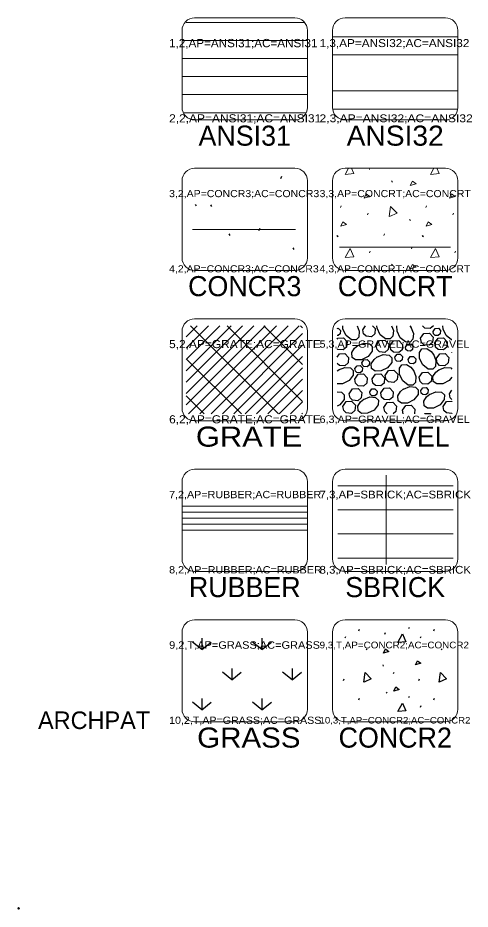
# Model space of a CAD drawing. Extents: x 95935 to 95946.4, y 95971.2 to 95974.7.
# Drawn here: x 95935.031 to 95936.835, y 95971.178 to 95974.732 of the extents above; entities that cross this region are included whole.
import ezdxf
from ezdxf.enums import TextEntityAlignment as Align

# ---------------------------------------------------------------- set-up
doc = ezdxf.new("R2010")
doc.units = 0
doc.header["$LTSCALE"] = 0.013
doc.header["$PDMODE"] = 32
doc.header["$PDSIZE"] = 0.0065
for name, color, linetype, lineweight in [('1', 7, 'Continuous', 13), ('25', 7, 'Continuous', 13), ('6', 7, 'Continuous', 13), ('63', 7, 'Continuous', 13)]:
    doc.layers.add(name, color=color, linetype=linetype, lineweight=lineweight)
doc.layers.add('20', color=7, linetype='Continuous')
doc.layers.add('8', color=7, linetype='Continuous')

msp = doc.modelspace()

# ---------------------------------------------------------------- linework, layer by layer
at = {"layer": '1'}
for p, q in [((95935.7357, 95974.7318), (95936.1357, 95974.7318)), ((95936.3357, 95974.7318), (95936.7357, 95974.7318)), ((95935.6857, 95974.3747), (95935.6857, 95974.6818)), ((95936.1857, 95974.6818), (95936.1857, 95974.3747)), ((95936.2857, 95974.3747), (95936.2857, 95974.6818)), ((95936.7857, 95974.6818), (95936.7857, 95974.3747)), ((95936.1357, 95974.3247), (95935.7357, 95974.3247)), ((95936.7357, 95974.3247), (95936.3357, 95974.3247)), ((95935.7357, 95974.1318), (95936.1357, 95974.1318)), ((95936.3357, 95974.1318), (95936.7357, 95974.1318)), ((95935.6857, 95973.7747), (95935.6857, 95974.0818)), ((95936.1857, 95974.0818), (95936.1857, 95973.7747)), ((95936.2857, 95973.7747), (95936.2857, 95974.0818)), ((95936.7857, 95974.0818), (95936.7857, 95973.7747)), ((95936.1357, 95973.7247), (95935.7357, 95973.7247)), ((95936.7357, 95973.7247), (95936.3357, 95973.7247)), ((95935.7357, 95973.5318), (95936.1357, 95973.5318)), ((95936.3357, 95973.5318), (95936.7357, 95973.5318)), ((95935.6857, 95973.1747), (95935.6857, 95973.4818)), ((95936.1857, 95973.4818), (95936.1857, 95973.1747)), ((95936.2857, 95973.1747), (95936.2857, 95973.4818)), ((95936.7857, 95973.4818), (95936.7857, 95973.1747)), ((95936.1357, 95973.1247), (95935.7357, 95973.1247)), ((95936.7357, 95973.1247), (95936.3357, 95973.1247)), ((95935.7357, 95972.9318), (95936.1357, 95972.9318)), ((95936.3357, 95972.9318), (95936.7357, 95972.9318)), ((95935.6857, 95972.5747), (95935.6857, 95972.8818)), ((95936.1857, 95972.8818), (95936.1857, 95972.5747)), ((95936.2857, 95972.5747), (95936.2857, 95972.8818)), ((95936.7857, 95972.8818), (95936.7857, 95972.5747)), ((95936.1357, 95972.5247), (95935.7357, 95972.5247)), ((95936.7357, 95972.5247), (95936.3357, 95972.5247)), ((95935.7357, 95972.3318), (95936.1357, 95972.3318)), ((95936.3357, 95972.3318), (95936.7357, 95972.3318)), ((95935.6857, 95971.9747), (95935.6857, 95972.2818)), ((95936.1857, 95972.2818), (95936.1857, 95971.9747)), ((95936.2857, 95971.9747), (95936.2857, 95972.2818)), ((95936.7857, 95972.2818), (95936.7857, 95971.9747)), ((95936.1357, 95971.9247), (95935.7357, 95971.9247)), ((95936.7357, 95971.9247), (95936.3357, 95971.9247))]:
    msp.add_line(p, q, dxfattribs=at)
for centre, start, end in [((95935.7357, 95974.6818), 90, 180), ((95936.1357, 95974.6818), 0, 90), ((95936.3357, 95974.6818), 90, 180), ((95936.7357, 95974.6818), 0, 90), ((95935.7357, 95974.3747), 180, 270), ((95936.1357, 95974.3747), 270, 0), ((95936.3357, 95974.3747), 180, 270), ((95936.7357, 95974.3747), 270, 0), ((95935.7357, 95974.0818), 90, 180), ((95936.1357, 95974.0818), 0, 90), ((95936.3357, 95974.0818), 90, 180), ((95936.7357, 95974.0818), 0, 90), ((95935.7357, 95973.7747), 180, 270), ((95936.1357, 95973.7747), 270, 0), ((95936.3357, 95973.7747), 180, 270), ((95936.7357, 95973.7747), 270, 0), ((95935.7357, 95973.4818), 90, 180), ((95936.1357, 95973.4818), 0, 90), ((95936.3357, 95973.4818), 90, 180), ((95936.7357, 95973.4818), 0, 90), ((95935.7357, 95973.1747), 180, 270), ((95936.1357, 95973.1747), 270, 0), ((95936.3357, 95973.1747), 180, 270), ((95936.7357, 95973.1747), 270, 0), ((95935.7357, 95972.8818), 90, 180), ((95936.1357, 95972.8818), 0, 90), ((95936.3357, 95972.8818), 90, 180), ((95936.7357, 95972.8818), 0, 90), ((95935.7357, 95972.5747), 180, 270), ((95936.1357, 95972.5747), 270, 0), ((95936.3357, 95972.5747), 180, 270), ((95936.7357, 95972.5747), 270, 0), ((95935.7357, 95972.2818), 90, 180), ((95936.1357, 95972.2818), 0, 90), ((95936.3357, 95972.2818), 90, 180), ((95936.7357, 95972.2818), 0, 90), ((95935.7357, 95971.9747), 180, 270), ((95936.1357, 95971.9747), 270, 0), ((95936.3357, 95971.9747), 180, 270), ((95936.7357, 95971.9747), 270, 0)]:
    msp.add_arc(centre, 0.05, start, end, dxfattribs=at)
at = {"layer": '25'}
msp.add_line((95935.7278, 95973.8875), (95936.1378, 95973.8875), dxfattribs=at)
at = {"layer": '6'}
for p, q in [((95935.7022, 95974.7136), (95936.1735, 95974.7136)), ((95935.6857, 95974.6416), (95936.1857, 95974.6416)), ((95936.2857, 95974.6561), (95936.7857, 95974.6561)), ((95935.6857, 95974.5696), (95936.1857, 95974.5696)), ((95936.2857, 95974.5841), (95936.7857, 95974.5841)), ((95935.6857, 95974.4976), (95936.1857, 95974.4976)), ((95935.6857, 95974.4256), (95936.1857, 95974.4256)), ((95936.2857, 95974.4401), (95936.7857, 95974.4401)), ((95935.6944, 95974.3536), (95936.1806, 95974.3536)), ((95936.2884, 95974.3681), (95936.7844, 95974.3681)), ((95936.3367, 95974.1077), (95936.3495, 95974.1318)), ((95936.4326, 95974.1269), (95936.4348, 95974.1318)), ((95936.677, 95974.1077), (95936.6898, 95974.1318)), ((95936.5214, 95974.0814), (95936.5243, 95974.0772)), ((95936.3175, 95973.9756), (95936.3204, 95973.982)), ((95936.6578, 95973.9756), (95936.6607, 95973.982)), ((95936.4255, 95973.9464), (95936.4284, 95973.9528)), ((95936.5944, 95973.9286), (95936.5951, 95973.9222)), ((95936.7658, 95973.9464), (95936.7687, 95973.9528)), ((95936.3026, 95973.864), (95936.3055, 95973.8598)), ((95936.3055, 95973.8624), (95936.3083, 95973.8582)), ((95936.4902, 95973.864), (95936.493, 95973.8704)), ((95936.6429, 95973.864), (95936.6458, 95973.8598)), ((95936.6458, 95973.8624), (95936.6486, 95973.8582)), ((95936.601, 95973.8114), (95936.6038, 95973.8178)), ((95936.4326, 95973.795), (95936.4355, 95973.8014)), ((95936.7729, 95973.795), (95936.7758, 95973.8014)), ((95936.5214, 95973.7496), (95936.5243, 95973.7453)), ((95935.7021, 95973.1884), (95936.0171, 95973.5038)), ((95935.7021, 95973.2336), (95935.9723, 95973.5038)), ((95935.7021, 95973.2788), (95935.9274, 95973.5038)), ((95935.7021, 95973.3241), (95935.8818, 95973.5038)), ((95935.7021, 95973.3694), (95935.8365, 95973.5038)), ((95935.7021, 95973.4146), (95935.7913, 95973.5038)), ((95935.7021, 95973.4599), (95935.746, 95973.5038)), ((95935.7113, 95973.1523), (95936.0628, 95973.5038)), ((95935.7199, 95973.5038), (95936.0698, 95973.1523)), ((95935.7566, 95973.1523), (95936.1086, 95973.5038)), ((95935.8018, 95973.1523), (95936.1533, 95973.5038)), ((95935.8652, 95973.5038), (95936.1667, 95973.2023)), ((95936.0122, 95973.5038), (95936.1667, 95973.3493)), ((95936.1585, 95973.5038), (95936.1667, 95973.4956)), ((95935.847, 95973.1523), (95936.1667, 95973.4725)), ((95935.8923, 95973.1523), (95936.1667, 95973.4267)), ((95935.7021, 95973.3727), (95935.9225, 95973.1523)), ((95935.9376, 95973.1523), (95936.1667, 95973.3814)), ((95935.9828, 95973.1523), (95936.1667, 95973.3362)), ((95936.0281, 95973.1523), (95936.1667, 95973.2909)), ((95935.7021, 95973.2244), (95935.7745, 95973.1523)), ((95936.0736, 95973.1523), (95936.1667, 95973.2453)), ((95936.1186, 95973.1523), (95936.1667, 95973.2004)), ((95936.1635, 95973.1523), (95936.1667, 95973.1555)), ((95936.4996, 95972.9082), (95936.4996, 95972.5517)), ((95936.3066, 95972.8659), (95936.7672, 95972.8659)), ((95935.6857, 95972.7846), (95936.1857, 95972.7846)), ((95935.6857, 95972.7606), (95936.1857, 95972.7606)), ((95936.3066, 95972.7699), (95936.7672, 95972.7699)), ((95935.6857, 95972.7366), (95936.1857, 95972.7366)), ((95935.6857, 95972.7126), (95936.1857, 95972.7126)), ((95935.6857, 95972.6886), (95936.1857, 95972.6886)), ((95936.3066, 95972.6739), (95936.7672, 95972.6739)), ((95936.3066, 95972.5779), (95936.7672, 95972.5779))]:
    msp.add_line(p, q, dxfattribs=at)
at = {"layer": '6', "lineweight": 25}
for p, q in [((95936.0799, 95974.0911), (95936.0842, 95974.1009)), ((95935.7379, 95973.9881), (95935.7422, 95973.9816)), ((95935.7994, 95973.9856), (95935.8037, 95973.9791)), ((95935.9925, 95973.8833), (95935.9968, 95973.893)), ((95935.8717, 95973.8707), (95935.8761, 95973.8642)), ((95936.1274, 95973.8142), (95936.1317, 95973.8078)), ((95936.4062, 95973.4882), (95936.4173, 95973.504)), ((95936.5938, 95973.504), (95936.5991, 95973.4973)), ((95936.3048, 95973.3241), (95936.3104, 95973.3286)), ((95936.7522, 95973.2331), (95936.7622, 95973.2472)), ((95936.5671, 95973.1527), (95936.5643, 95973.167)), ((95936.3903, 95972.2883), (95936.393, 95972.2943)), ((95936.589, 95972.3013), (95936.5917, 95972.2973)), ((95936.6903, 95972.2883), (95936.693, 95972.2943)), ((95936.3364, 95972.2591), (95936.3391, 95972.2651)), ((95936.4942, 95972.2744), (95936.4969, 95972.2804)), ((95936.6364, 95972.2591), (95936.6391, 95972.2651)), ((95935.7643, 95972.2129), (95935.8018, 95972.2429)), ((95936.0043, 95972.2129), (95936.0418, 95972.2429)), ((95936.4196, 95972.2165), (95936.4223, 95972.2125)), ((95936.7196, 95972.2165), (95936.7223, 95972.2125)), ((95936.487, 95972.1526), (95936.4876, 95972.1466)), ((95935.8843, 95972.0929), (95935.8468, 95972.1229)), ((95936.1243, 95972.0929), (95936.0868, 95972.1229)), ((95936.5285, 95972.1172), (95936.5312, 95972.1232)), ((95936.3297, 95972.0899), (95936.3324, 95972.0959)), ((95936.6297, 95972.0899), (95936.6324, 95972.0959)), ((95936.4993, 95972.0426), (95936.5019, 95972.0386)), ((95936.3903, 95972.0127), (95936.393, 95972.0187)), ((95936.589, 95972.0257), (95936.5917, 95972.0217)), ((95936.6903, 95972.0127), (95936.693, 95972.0187)), ((95935.7643, 95971.9729), (95935.8018, 95972.0029)), ((95936.0043, 95971.9729), (95936.0418, 95972.0029)), ((95936.6364, 95971.9834), (95936.6391, 95971.9894))]:
    msp.add_line(p, q, dxfattribs=at)
at = {"layer": '6'}
for points in [[(95936.3613, 95974.1318), (95936.3708, 95974.1106), (95936.3374, 95974.1077)], [(95936.7016, 95974.1318), (95936.7111, 95974.1106), (95936.6777, 95974.1077)], [(95936.512, 95973.9391), (95936.5176, 95973.9797), (95936.543, 95973.9534), (95936.5126, 95973.9393)], [(95936.3367, 95973.7759), (95936.3559, 95973.8121), (95936.3708, 95973.7787), (95936.3374, 95973.7759)], [(95936.677, 95973.7759), (95936.6962, 95973.8121), (95936.7111, 95973.7787), (95936.6777, 95973.7759)]]:
    msp.add_lwpolyline(points, dxfattribs=at)
for points in [[(95936.596, 95974.063), (95936.6045, 95974.0807), (95936.6188, 95974.0701)], [(95936.4115, 95974.0122), (95936.42, 95974.0299), (95936.4342, 95974.0193)], [(95936.7518, 95974.0122), (95936.7603, 95974.0299), (95936.7745, 95974.0193)], [(95936.319, 95973.901), (95936.3275, 95973.9187), (95936.3417, 95973.9081)], [(95936.6593, 95973.901), (95936.6678, 95973.9187), (95936.682, 95973.9081)], [(95936.596, 95973.7311), (95936.6045, 95973.7489), (95936.6188, 95973.7382)]]:
    msp.add_lwpolyline(points, close=True, dxfattribs=at)
at = {"layer": '6', "lineweight": 25}
for points in [[(95936.3834, 95973.504), (95936.3921, 95973.4821), (95936.3901, 95973.459), (95936.3796, 95973.448), (95936.3609, 95973.4484), (95936.3396, 95973.465), (95936.3267, 95973.4908), (95936.3265, 95973.504)], [(95936.4456, 95973.504), (95936.4561, 95973.4931), (95936.4539, 95973.4714), (95936.4407, 95973.4604), (95936.4195, 95973.4619), (95936.4095, 95973.4716), (95936.4063, 95973.4882)], [(95936.5213, 95973.504), (95936.5287, 95973.4854), (95936.5267, 95973.4622), (95936.5163, 95973.4513), (95936.4975, 95973.4516), (95936.4762, 95973.4683), (95936.4633, 95973.494), (95936.4631, 95973.504)], [(95936.5985, 95973.4983), (95936.6084, 95973.4732), (95936.6064, 95973.45), (95936.596, 95973.4391), (95936.5772, 95973.4394), (95936.5559, 95973.4561), (95936.5431, 95973.4818), (95936.5426, 95973.504)], [(95936.6884, 95973.504), (95936.6751, 95973.4929), (95936.6539, 95973.4945), (95936.6441, 95973.504)], [(95936.7622, 95973.4484), (95936.7606, 95973.4484), (95936.7393, 95973.465), (95936.7265, 95973.4908), (95936.7262, 95973.504)], [(95936.3048, 95973.4936), (95936.3081, 95973.4938), (95936.317, 95973.4845), (95936.3158, 95973.4715), (95936.3078, 95973.4649), (95936.3048, 95973.4651)], [(95936.3048, 95973.4508), (95936.3074, 95973.4545), (95936.3289, 95973.4557), (95936.3438, 95973.4402), (95936.3417, 95973.4185), (95936.3284, 95973.4075), (95936.3072, 95973.4091), (95936.3048, 95973.4114)], [(95936.3851, 95973.4241), (95936.4102, 95973.4341), (95936.4333, 95973.4321), (95936.4443, 95973.4217), (95936.4439, 95973.4029), (95936.4273, 95973.3816), (95936.4015, 95973.3687), (95936.3772, 95973.3683), (95936.3636, 95973.378), (95936.3623, 95973.3973), (95936.3734, 95973.4146), (95936.3861, 95973.4248)], [(95936.5765, 95973.4192), (95936.5846, 95973.4306), (95936.5975, 95973.4314), (95936.6064, 95973.4221), (95936.6051, 95973.4091), (95936.5972, 95973.4025), (95936.5845, 95973.4034), (95936.5785, 95973.4092), (95936.5765, 95973.4191)], [(95936.6938, 95973.4354), (95936.7072, 95973.4545), (95936.7287, 95973.4557), (95936.7436, 95973.4402), (95936.7414, 95973.4185), (95936.7282, 95973.4075), (95936.707, 95973.4091), (95936.697, 95973.4187), (95936.6938, 95973.4353)], [(95936.3048, 95973.3793), (95936.3134, 95973.3916), (95936.3349, 95973.3928), (95936.3498, 95973.3773), (95936.3477, 95973.3556), (95936.3344, 95973.3446), (95936.3132, 95973.3461), (95936.3048, 95973.3542)], [(95936.4631, 95973.3792), (95936.4882, 95973.3892), (95936.5113, 95973.3872), (95936.5223, 95973.3767), (95936.522, 95973.358), (95936.5053, 95973.3367), (95936.4796, 95973.3238), (95936.4553, 95973.3234), (95936.4416, 95973.3331), (95936.4403, 95973.3524), (95936.4514, 95973.3697), (95936.4641, 95973.3798)], [(95936.6883, 95973.3901), (95936.6983, 95973.365), (95936.6963, 95973.3419), (95936.6859, 95973.3309), (95936.6671, 95973.3312), (95936.6458, 95973.3479), (95936.6329, 95973.3737), (95936.6325, 95973.3979), (95936.6422, 95973.4116), (95936.6615, 95973.4129), (95936.6788, 95973.4018), (95936.689, 95973.3891)], [(95936.6997, 95973.3724), (95936.7132, 95973.3916), (95936.7347, 95973.3928), (95936.7496, 95973.3773), (95936.7474, 95973.3556), (95936.7342, 95973.3446), (95936.713, 95973.3461), (95936.703, 95973.3558), (95936.6998, 95973.3724)], [(95936.7622, 95973.3957), (95936.7621, 95973.3973), (95936.7622, 95973.3975)], [(95936.3094, 95973.328), (95936.3345, 95973.3379), (95936.3576, 95973.3359), (95936.3686, 95973.3255), (95936.3683, 95973.3067), (95936.3516, 95973.2854), (95936.3258, 95973.2726), (95936.3048, 95973.2722)], [(95936.6082, 95973.3267), (95936.6182, 95973.3015), (95936.6162, 95973.2784), (95936.6057, 95973.2674), (95936.587, 95973.2678), (95936.5657, 95973.2845), (95936.5528, 95973.3102), (95936.5524, 95973.3345), (95936.5621, 95973.3482), (95936.5814, 95973.3494), (95936.5987, 95973.3384), (95936.6089, 95973.3257)], [(95936.7622, 95973.2993), (95936.7514, 95973.2854), (95936.7256, 95973.2726), (95936.7013, 95973.2721), (95936.6877, 95973.2818), (95936.6864, 95973.3012), (95936.6975, 95973.3185), (95936.7102, 95973.3286)], [(95936.7091, 95973.328), (95936.7343, 95973.3379), (95936.7574, 95973.3359), (95936.7622, 95973.3314)], [(95936.434, 95973.2409), (95936.4421, 95973.2524), (95936.455, 95973.2531), (95936.464, 95973.2438), (95936.4627, 95973.2308), (95936.4547, 95973.2242), (95936.442, 95973.2251), (95936.436, 95973.2309), (95936.4341, 95973.2409)], [(95936.5683, 95973.2513), (95936.5935, 95973.2612), (95936.6166, 95973.2592), (95936.6276, 95973.2488), (95936.6272, 95973.23), (95936.6106, 95973.2087), (95936.5848, 95973.1959), (95936.5605, 95973.1954), (95936.5469, 95973.2051), (95936.5456, 95973.2245), (95936.5567, 95973.2418), (95936.5694, 95973.2519)], [(95936.3048, 95973.24), (95936.3211, 95973.2386), (95936.332, 95973.2281), (95936.3317, 95973.2094), (95936.315, 95973.1881), (95936.3048, 95973.183)], [(95936.4095, 95973.2103), (95936.4346, 95973.2202), (95936.4577, 95973.2182), (95936.4687, 95973.2078), (95936.4683, 95973.1891), (95936.4517, 95973.1678), (95936.4259, 95973.1549), (95936.4016, 95973.1544), (95936.388, 95973.1642), (95936.3867, 95973.1835), (95936.3978, 95973.2008), (95936.4105, 95973.2109)], [(95936.6726, 95973.2306), (95936.6977, 95973.2406), (95936.7208, 95973.2386), (95936.7318, 95973.2281), (95936.7315, 95973.2094), (95936.7148, 95973.1881), (95936.689, 95973.1752), (95936.6648, 95973.1748), (95936.6511, 95973.1845), (95936.6498, 95973.2038), (95936.6609, 95973.2211), (95936.6736, 95973.2313)], [(95936.7622, 95973.21), (95936.7555, 95973.2164), (95936.7522, 95973.2331)], [(95936.4908, 95973.1787), (95936.5042, 95973.1978), (95936.5257, 95973.1991), (95936.5406, 95973.1836), (95936.5384, 95973.1619), (95936.5274, 95973.1527)], [(95936.5037, 95973.1527), (95936.494, 95973.1621), (95936.4908, 95973.1787)], [(95936.5643, 95973.167), (95936.5777, 95973.1861), (95936.5992, 95973.1873), (95936.6141, 95973.1719), (95936.6122, 95973.1527)], [(95936.7269, 95973.1825), (95936.7404, 95973.2016), (95936.7618, 95973.2028), (95936.7622, 95973.2024)], [(95936.7622, 95973.1553), (95936.7614, 95973.1546), (95936.7402, 95973.1562), (95936.7302, 95973.1658), (95936.7269, 95973.1825)], [(95936.6536, 95973.1527), (95936.6542, 95973.1536), (95936.6756, 95973.1548), (95936.6776, 95973.1527)], [(95935.7643, 95972.2579), (95935.7643, 95972.2129), (95935.7268, 95972.2429)], [(95936.0043, 95972.2579), (95936.0043, 95972.2129), (95935.9668, 95972.2429)], [(95936.5465, 95972.2411), (95936.5645, 95972.2751), (95936.5784, 95972.2438), (95936.5471, 95972.2411)], [(95935.8843, 95972.1379), (95935.8843, 95972.0929), (95935.9218, 95972.1229)], [(95936.1243, 95972.1379), (95936.1243, 95972.0929), (95936.1618, 95972.1229)], [(95936.4108, 95972.083), (95936.416, 95972.1211), (95936.4399, 95972.0965), (95936.4114, 95972.0833)], [(95936.7108, 95972.083), (95936.716, 95972.1211), (95936.7399, 95972.0965), (95936.7114, 95972.0833)], [(95935.7643, 95972.0179), (95935.7643, 95971.9729), (95935.7268, 95972.0029)], [(95936.0043, 95972.0179), (95936.0043, 95971.9729), (95935.9668, 95972.0029)], [(95936.5465, 95971.9655), (95936.5645, 95971.9994), (95936.5784, 95971.9681), (95936.5471, 95971.9655)]]:
    msp.add_lwpolyline(points, dxfattribs=at)
for points in [[(95936.637, 95973.4543), (95936.6504, 95973.4735), (95936.6719, 95973.4747), (95936.6868, 95973.4592), (95936.6846, 95973.4375), (95936.6714, 95973.4265), (95936.6502, 95973.428), (95936.6402, 95973.4377)], [(95936.6869, 95973.4816), (95936.695, 95973.493), (95936.7079, 95973.4938), (95936.7168, 95973.4845), (95936.7155, 95973.4715), (95936.7076, 95973.4649), (95936.6948, 95973.4658), (95936.6889, 95973.4716)], [(95936.4601, 95973.4259), (95936.4735, 95973.445), (95936.495, 95973.4462), (95936.5099, 95973.4308), (95936.5077, 95973.4091), (95936.4945, 95973.398), (95936.4733, 95973.3996), (95936.4633, 95973.4092)], [(95936.5154, 95973.4251), (95936.5288, 95973.4442), (95936.5503, 95973.4454), (95936.5652, 95973.4299), (95936.563, 95973.4083), (95936.5498, 95973.3972), (95936.5286, 95973.3988), (95936.5186, 95973.4084)], [(95936.5349, 95973.3788), (95936.543, 95973.3903), (95936.5559, 95973.391), (95936.5648, 95973.3817), (95936.5635, 95973.3687), (95936.5556, 95973.3621), (95936.5429, 95973.363), (95936.5369, 95973.3688)], [(95936.4032, 95973.3567), (95936.4112, 95973.3682), (95936.4241, 95973.3689), (95936.4331, 95973.3597), (95936.4318, 95973.3467), (95936.4238, 95973.34), (95936.4111, 95973.341), (95936.4051, 95973.3468)], [(95936.5879, 95973.3693), (95936.596, 95973.3808), (95936.6088, 95973.3816), (95936.6178, 95973.3723), (95936.6165, 95973.3593), (95936.6085, 95973.3526), (95936.5958, 95973.3536), (95936.5898, 95973.3594)], [(95936.3754, 95973.3334), (95936.3835, 95973.3449), (95936.3964, 95973.3456), (95936.4053, 95973.3363), (95936.404, 95973.3233), (95936.3961, 95973.3167), (95936.3833, 95973.3176), (95936.3774, 95973.3234)], [(95936.496, 95973.3062), (95936.5095, 95973.3253), (95936.5309, 95973.3265), (95936.5459, 95973.3111), (95936.5437, 95973.2894), (95936.5304, 95973.2784), (95936.5093, 95973.2799), (95936.4993, 95973.2896)], [(95936.6316, 95973.2985), (95936.6451, 95973.3176), (95936.6665, 95973.3188), (95936.6814, 95973.3033), (95936.6793, 95973.2817), (95936.666, 95973.2706), (95936.6448, 95973.2722), (95936.6349, 95973.2818)], [(95936.3745, 95973.2914), (95936.388, 95973.3105), (95936.4094, 95973.3117), (95936.4244, 95973.2963), (95936.4222, 95973.2746), (95936.4089, 95973.2635), (95936.3877, 95973.2651), (95936.3778, 95973.2747)], [(95936.4439, 95973.2922), (95936.4573, 95973.3113), (95936.4788, 95973.3125), (95936.4937, 95973.297), (95936.4916, 95973.2754), (95936.4783, 95973.2643), (95936.4571, 95973.2659), (95936.4471, 95973.2755)], [(95936.3525, 95973.2331), (95936.3659, 95973.2522), (95936.3874, 95973.2534), (95936.4023, 95973.2379), (95936.4001, 95973.2163), (95936.3869, 95973.2052), (95936.3657, 95973.2068), (95936.3557, 95973.2164)], [(95936.4781, 95973.236), (95936.4916, 95973.2551), (95936.513, 95973.2563), (95936.5279, 95973.2408), (95936.5258, 95973.2192), (95936.5125, 95973.2081), (95936.4913, 95973.2097), (95936.4814, 95973.2193)], [(95936.6377, 95973.2453), (95936.6458, 95973.2568), (95936.6587, 95973.2575), (95936.6676, 95973.2483), (95936.6663, 95973.2353), (95936.6584, 95973.2286), (95936.6457, 95973.2296), (95936.6397, 95973.2354)], [(95936.3272, 95973.1825), (95936.3406, 95973.2016), (95936.3621, 95973.2028), (95936.377, 95973.1873), (95936.3748, 95973.1657), (95936.3616, 95973.1546), (95936.3404, 95973.1562), (95936.3304, 95973.1658)], [(95936.4896, 95972.1991), (95936.4976, 95972.2158), (95936.5109, 95972.2058)], [(95936.6165, 95972.1515), (95936.6245, 95972.1682), (95936.6378, 95972.1582)], [(95936.5298, 95972.0473), (95936.5378, 95972.0639), (95936.5511, 95972.0539)]]:
    msp.add_lwpolyline(points, close=True, dxfattribs=at)
at = {"layer": '63'}
msp.add_line((95936.7569, 95973.8178), (95936.3141, 95973.8178), dxfattribs=at)
msp.add_point((95935.0341, 95971.1811), dxfattribs=at)

# ---------------------------------------------------------------- texts
at = {"layer": '20'}
for s, p in [('ANSI31', (95935.9357, 95974.222)), ('CONCR3', (95935.9357, 95973.622)), ('CONCRT', (95936.5358, 95973.622)), ('GRAVEL', (95936.5357, 95973.022)), ('RUBBER', (95935.9358, 95972.422)), ('SBRICK', (95936.5358, 95972.422)), ('CONCR2', (95936.5359, 95971.822))]:
    msp.add_text(s, height=0.08, dxfattribs=at).set_placement(p, align=Align.CENTER)
for s, width, p in [('ANSI32', 1.05, (95936.5357, 95974.222)), (' GRATE', 1.15, (95935.9358, 95973.022)), (' GRASS', 1.1, (95935.9357, 95971.822))]:
    msp.add_text(s, height=0.08, dxfattribs=dict(at, width=width)).set_placement(p, align=Align.CENTER)
at = {"layer": '63'}
for s, height, width, p in [('1,2,AP=ANSI31;AC=ANSI31', 0.0331, 1.05, (95935.6341, 95974.6145)), ('1,3,AP=ANSI32;AC=ANSI32', 0.0319, 1.1, (95936.2341, 95974.6151)), ('2,2,AP=ANSI31;AC=ANSI31', 0.0324, 1.1, (95935.6341, 95974.3149)), ('2,3,AP=ANSI32;AC=ANSI32', 0.0312, 1.15, (95936.2341, 95974.3155)), ('3,2,AP=CONCR3;AC=CONCR3', 0.0285, 1.1, (95935.6341, 95974.0168)), ('3,3,AP=CONCRT;AC=CONCRT', 0.0285, 1.1, (95936.2341, 95974.0168)), ('4,2,AP=CONCR3;AC=CONCR3', 0.0284, 1.1, (95935.6341, 95973.7169)), ('4,3,AP=CONCRT;AC=CONCRT', 0.0284, 1.1, (95936.2341, 95973.7169)), ('5,2,AP=GRATE;AC=GRATE', 0.0323, 1.1, (95935.6341, 95973.4149)), ('5,3,AP=GRAVEL;AC=GRAVEL', 0.0291, 1.1, (95936.2341, 95973.4165)), ('6,2,AP=GRATE;AC=GRATE', 0.0323, 1.1, (95935.6341, 95973.1149)), ('6,3,AP=GRAVEL;AC=GRAVEL', 0.0292, 1.1, (95936.2341, 95973.1165)), ('7,2,AP=RUBBER;AC=RUBBER', 0.0291, 1.1, (95935.6341, 95972.8165)), ('7,3,AP=SBRICK;AC=SBRICK', 0.0309, 1.1, (95936.2341, 95972.8156)), ('8,2,AP=RUBBER;AC=RUBBER', 0.0292, 1.1, (95935.6341, 95972.5165)), ('8,3,AP=SBRICK;AC=SBRICK', 0.0309, 1.1, (95936.2341, 95972.5156)), ('9,2,T,AP=GRASS;AC=GRASS', 0.0298, 1.1, (95935.6341, 95972.2162)), ('9,3,T,AP=CONCR2;AC=CONCR2', 0.0267, 1.1, (95936.2341, 95972.2177)), ('10,2,T,AP=GRASS;AC=GRASS', 0.0289, 1.1, (95935.6341, 95971.9166)), ('10,3,T,AP=CONCR2;AC=CONCR2', 0.026, 1.1, (95936.2341, 95971.9181))]:
    msp.add_text(s, height=height, dxfattribs=dict(at, width=width)).set_placement(p)
at = {"layer": '8'}
msp.add_text('ARCHPAT', height=0.07, dxfattribs=at).set_placement((95935.335, 95971.8961), align=Align.CENTER)

doc.saveas('drawing.dxf')
